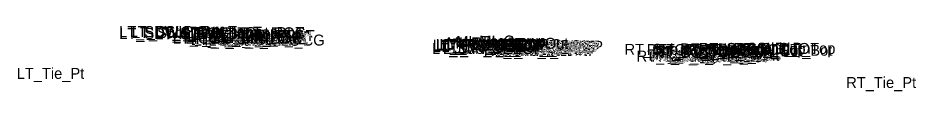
# Model space of a CAD drawing. Extents: x 0 to 4229, y -1 to 9523.
# Drawn here: x 1064.8 to 1228.9, y 5505.7 to 5517.6 of the extents above; entities that cross this region are included whole.
import ezdxf

# ---------------------------------------------------------------- set-up
doc = ezdxf.new("R2010")
doc.units = 0
doc.layers.add('Default', color=7, linetype='Continuous')

msp = doc.modelspace()

# ---------------------------------------------------------------- texts
at = {"layer": 'Default'}
for s, p in [('LT_SDWK_Out_Top', (1083.24, 5515.52)), ('LT_SDWK_Out_Bot', (1083.27, 5515.19)), ('LT_CSLP_Pnt', (1085.17, 5515.55)), ('LT_Sub_Trench_Out_DLT', (1085.58, 5515.35)), ('LT_SDWK_In_Top', (1089.86, 5515.42)), ('LT_SDWK_In_Bot', (1089.89, 5515.09)), ('LT_CG_Top_Face', (1094.76, 5515.31)), ('LT_CG_Top_BOC', (1095.28, 5515.31)), ('LT_CG1_Shelf_Out', (1093.05, 5514.34)), ('LT_CG_Bot_BOC', (1095.31, 5514.32)), ('LT_CG_Top_Gut', (1095.74, 5514.81)), ('LT_Sub_OEOP', (1096.37, 5514.1)), ('LT_Sub_OEOT_CG', (1096.87, 5513.98)), ('LT_CG_Bot_IE', (1099.41, 5514.23)), ('LT_Sub_OEOT', (1099.58, 5513.94)), ('LT_PV2_OEOT', (1099.67, 5514.57)), ('LT_PV3_OEOT', (1099.67, 5514.32)), ('LT_PV1_OEOT', (1100.24, 5514.82)), ('MI_Face In', (1143.15, 5513.48)), ('MI_Top In', (1144.86, 5513.73)), ('MI_Crown', (1149.07, 5513.81)), ('MI_Top Out', (1151.22, 5513.39)), ('LT_Sub_OEEOP', (1140.46, 5512.44)), ('LT_PV2_OEEOP', (1140.56, 5513.06)), ('LT_PV3_OEEOP', (1140.56, 5512.81)), ('LT_PV1_OEEOP', (1141.12, 5513.19)), ('LT_PV2_IEEOP', (1141.2, 5513.06)), ('LT_PV1_IEEOP', (1141.77, 5513.19)), ('LT_PV2_PGL1', (1142.13, 5513.06)), ('LT_PV3_PGL1', (1142.13, 5512.81)), ('LT_PV2_PGL', (1142.46, 5513.06)), ('LT_PV4_PGL', (1142.46, 5512.44)), ('LT_PV1_PGL', (1143.03, 5513.31)), ('MI_Bot In', (1144.13, 5513.31)), ('RT_Sub_OEEOP', (1149.92, 5512.1)), ('RT_PV2_OEEOP', (1150.01, 5512.72)), ('RT_PV3_OEEOP', (1150.01, 5512.47)), ('RT_PV1_OEEOP', (1150.58, 5512.85)), ('RT_PV2_IEEOP', (1150.66, 5512.72)), ('MI_Face Out', (1151.01, 5513.14)), ('RT_PV1_IEEOP', (1151.22, 5512.85)), ('RT_PV2_PGL1', (1151.58, 5512.72)), ('RT_PV3_PGL1', (1151.58, 5512.47)), ('RT_PV2_PGL', (1151.92, 5512.72)), ('RT_PV4_PGL', (1151.92, 5512.1)), ('MI_Bot Out', (1152.01, 5512.97)), ('RT_PV1_PGL', (1152.48, 5512.97)), ('RT_Sub_Trench_Out_DLT', (1175.62, 5512.29)), ('RT_CG_Top_Face', (1179.71, 5512.25)), ('RT_CG_Top_Gut', (1180.69, 5511.75)), ('RT_PV1_OEOT', (1181.19, 5511.9)), ('RT_CG_Top_BOC', (1181.24, 5512.25)), ('RT_SDWK_In_Top', (1185.81, 5512.36)), ('RT_SDWK_In_Bot', (1185.84, 5512.03)), ('RT_SDWK_Out_Top', (1189.19, 5512.46)), ('RT_SDWK_Out_Bot', (1189.22, 5512.13)), ('RT_Shld_O', (1195.54, 5512.45)), ('CSLP_Pnt', (1197.87, 5512.49)), ('RT_Sub_OEOT_CG', (1177.82, 5511.07)), ('RT_CG1_Shelf_Out', (1180, 5511.21)), ('RT_CG_Bot_IE', (1180.37, 5511.32)), ('RT_Sub_OEOT', (1180.53, 5511.03)), ('RT_PV2_OEOT', (1180.63, 5511.65)), ('RT_PV3_OEOT', (1180.63, 5511.4)), ('RT_CG_Bot_BOC', (1181.27, 5511.23)), ('RT_Sub_OEOP', (1183.82, 5510.95)), ('LT_Tie_Pt', (1064.53, 5507.91)), ('RT_Tie_Pt', (1216.14, 5506.24))]:
    msp.add_text(s, height=2, dxfattribs=at).set_placement(p)

doc.saveas('drawing.dxf')
